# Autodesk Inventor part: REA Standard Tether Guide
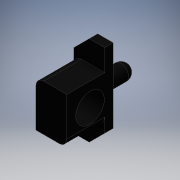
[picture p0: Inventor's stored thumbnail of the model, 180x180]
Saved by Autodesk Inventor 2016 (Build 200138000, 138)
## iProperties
Created: 2015-05
Part Number: REA Standard Tether Guide
Material: Generic
Document SubType Name: Modeling
Designer: Brett
Density: 1 g/cm^3
Appearance: Black
Author: Brett
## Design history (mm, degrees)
sketch "Sketch1"
  geometry: L1 (-3, 3)-(3, 3); L2 (3, 3)-(3, -3); L3 (3, -3)-(-3, -3); L4 (-3, -3)-(-3, 3); L5 (-3, 3)-(3, -3); L6 (3, 3)-(-3, -3); C1 r 1.85 at (0, 0); 1 further point
  constraints: 12 end point, 2 midpoint, 2 parallel, 1 centre point, 1 coincident, 1 horizontal, 1 perpendicular
  dimensions: "d0" = 3.7 diameter of C1; "d1" = 6 distance of L2.end L3.end; "d2" = 6 distance of L1.end L2.end
extrude "Extrusion1" new body sketch "Sketch1" distance "d3" = 4; taper "d4" = 0 deg
sketch "Sketch2"
  geometry: C1 r 1 at (2, 3); 1 further point
  constraints: 1 centre point
  dimensions: "d5" = 2 diameter of C1; "d6" = 2 distance of C1.centre point (0, 3)
extrude "Extrusion2" join sketch "Sketch2" distance "d7" = 4; taper "d8" = 0 deg
sketch "Sketch3"
  geometry: L1 (0, 6)-(4, 6) reference; L2 (0, 6)-(0, 8.8); L3 (0, 8.8)-(2, 8.8); L4 (2, 8.8)-(4, 6.8); L5 (4, 6.8)-(4, 6); L6 (4, 0)-(4, -2.8); L7 (4, -2.8)-(2, -2.8); L8 (2, -2.8)-(0, -0.8); L9 (0, -0.8)-(0, 0); L10 (0, 6)-(4, 6); L11 (4, 0)-(0, 0); 1 further point
  constraints: 20 end point, 2 parallel, 2 perpendicular, 2 vertical, 1 collinear, 1 horizontal
  dimensions: "d9" = 2.8 distance of L1.start L2.end; "d10" = 2 distance of L2.end L3.end; "d11" = 45 deg angle of L4 L3; "d12" = 2.8 distance of L6.start L6.end; "d13" = 2 distance of L6.end L7.end; "d14" = 45 deg angle of L8 L7
extrude "Extrusion3" join sketch "Sketch3" distance "d15" = 1.1; taper "d16" = 0 deg
fillet "Fillet1" dims "d17" = 1
body "Solid1"
